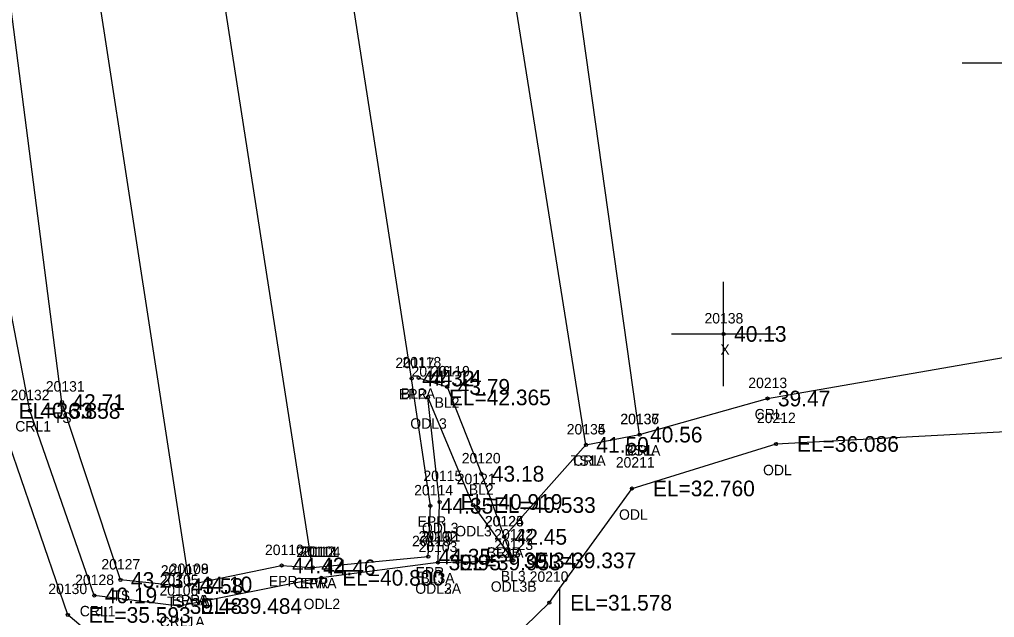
# Model space of a CAD drawing. Extents: x 2619569 to 2620117, y 784503 to 785150.
# Drawn here: x 2619804.3 to 2619897.7, y 784842.3 to 784899.6 of the extents above; entities that cross this region are included whole.
import ezdxf

# ---------------------------------------------------------------- set-up
doc = ezdxf.new("R2010")
doc.units = 0
for name, color, linetype in [('RD_DTM_BkLn1', 7, 'Continuous'), ('RD_DTM_BkLn2', 7, 'Continuous'), ('RD_DTM_BkLn_txCode', 7, 'Continuous'), ('RD_EX_H2O', 7, 'Continuous'), ('RD_EX_H2O_txCode', 7, 'Continuous'), ('RD_EX_Misc', 7, 'Continuous'), ('RD_EX_Misc_txCode', 7, 'Continuous'), ('RD_EX_Road', 7, 'Continuous'), ('RD_EX_Road_txCode', 7, 'Continuous'), ('RD_EX_TX_H2O_ELEV', 7, 'Continuous'), ('RD_EX_TX_Misc_ELEV', 7, 'Continuous'), ('RD_EX_TX_Road_ELEV', 7, 'Continuous'), ('RD_HC_Survey_ELEV', 7, 'Continuous'), ('RD_HC_Survey_txCode', 7, 'Continuous'), ('RD_SMD_Locator', 7, 'Continuous')]:
    doc.layers.add(name, color=color, linetype=linetype)

msp = doc.modelspace()

# ---------------------------------------------------------------- linework, layer by layer
at = {"layer": 'RD_DTM_BkLn1'}
for points in [[(2619832.403, 784847.117), (2619818.356, 784937.353), (2619803.195, 785033.818), (2619788.168, 785128.621)], [(2619842.547, 784865.279), (2619845.285, 784864.417), (2619848.555, 784856.083), (2619850.743, 784850.045)], [(2619844.412, 784847.589), (2619851.623, 784847.784), (2619850.743, 784850.045)]]:
    msp.add_lwpolyline(points, dxfattribs=at)
at = {"layer": 'RD_DTM_BkLn2'}
for points in [[(2619863.707, 784859.835), (2619852.265, 784941.112), (2619844.138, 785034.207), (2619822.185, 785133.612)], [(2619858.565, 784858.854), (2619845.668, 784939.8), (2619836.135, 785033.438), (2619815.075, 785132.906)], [(2619819.736, 784845.328), (2619814.007, 784845.916), (2619808.402, 784862.96), (2619799.163, 784934.374), (2619781.539, 785030.114), (2619769.886, 785089.145), (2619763.914, 785131.014)]]:
    msp.add_lwpolyline(points, dxfattribs=at)
at = {"layer": 'RD_EX_H2O'}
for points in [[(2619818.975, 784834.059), (2619808.965, 784842.559), (2619802.242, 784862.109), (2619788.776, 784932.49), (2619768.719, 785027.955), (2619758.968, 785087.806)], [(2619819.632, 784843.412), (2619811.497, 784844.429), (2619805.322, 784862.135), (2619791.728, 784933.025)], [(2619850.743, 784850.045), (2619858.565, 784858.854), (2619863.707, 784859.835), (2619875.949, 784863.297), (2619903.666, 784868.121), (2619924.462, 784867.36), (2619949.256, 784874.613), (2619971.299, 784850.547), (2619990.936, 784832.204), (2619978.094, 784805.139), (2619980.544, 784803.04), (2620013.789, 784776.159)], [(2619849.213, 784838.053), (2619855.055, 784843.735), (2619862.979, 784854.681), (2619876.772, 784858.944), (2619905.894, 784860.527), (2619923.246, 784863.85), (2619948.053, 784872.759), (2619969.079, 784848.673), (2619985.638, 784830.75), (2619975.853, 784807.963), (2619978.047, 784802.932), (2620013.477, 784773.679)], [(2619844.412, 784847.589), (2619844.558, 784853.388), (2619843.445, 784863.402), (2619847.748, 784853.09), (2619851.623, 784847.784)], [(2619844.412, 784847.589), (2619833.229, 784846.116), (2619819.632, 784843.412)]]:
    msp.add_lwpolyline(points, dxfattribs=at)
at = {"layer": 'RD_EX_Misc'}
for p, q in [((2619894.595, 784895.444), (2619904.595, 784895.444)), ((2619871.754, 784864.487), (2619871.754, 784874.487)), ((2619866.754, 784869.487), (2619876.754, 784869.487)), ((2619856.078, 784835.186), (2619856.078, 784845.186))]:
    msp.add_line(p, q, dxfattribs=at)
at = {"layer": 'RD_EX_Road'}
for points in [[(2619820.599, 784845.483), (2619829.428, 784847.299), (2619832.403, 784847.117), (2619843.469, 784848.147), (2619843.673, 784853.016), (2619841.879, 784865.21), (2619830.537, 784938.018), (2619815.779, 785030.404), (2619811.398, 785059.133), (2619800.292, 785130.224)], [(2619820.599, 784845.483), (2619806.714, 784935.634), (2619791.636, 785032.008), (2619776.959, 785126.604)]]:
    msp.add_lwpolyline(points, dxfattribs=at)
at = {"layer": 'RD_SMD_Locator'}
for centre in [(2619871.754, 784869.487), (2619842.547, 784865.279), (2619841.879, 784865.21), (2619845.285, 784864.417), (2619843.445, 784863.402), (2619808.402, 784862.96), (2619875.949, 784863.297), (2619805.322, 784862.135), (2619863.707, 784859.835), (2619863.707, 784859.835), (2619858.565, 784858.854), (2619858.565, 784858.854), (2619876.772, 784858.944), (2619848.555, 784856.083), (2619862.979, 784854.681), (2619844.558, 784853.388), (2619843.673, 784853.016), (2619847.748, 784853.09), (2619850.743, 784850.045), (2619850.743, 784850.045), (2619850.743, 784850.045), (2619843.469, 784848.147), (2619844.412, 784847.589), (2619844.412, 784847.589), (2619844.412, 784847.589), (2619851.623, 784847.784), (2619851.623, 784847.784), (2619829.428, 784847.299), (2619832.403, 784847.117), (2619832.403, 784847.117), (2619814.007, 784845.916), (2619833.229, 784846.116), (2619819.736, 784845.328), (2619820.599, 784845.483), (2619820.599, 784845.483), (2619811.497, 784844.429), (2619819.632, 784843.412), (2619819.632, 784843.412), (2619855.055, 784843.735), (2619808.965, 784842.559)]:
    msp.add_circle(centre, 0.15, dxfattribs=at)

# ---------------------------------------------------------------- texts
at = {"layer": 'RD_DTM_BkLn_txCode'}
for s, p in [('20118', (2619840.995, 784866.279)), ('20119', (2619843.734, 784865.417)), ('20131', (2619806.851, 784863.96)), ('BL2A', (2619840.854, 784863.279)), ('BL2', (2619844.081, 784862.417)), ('TS', (2619807.607, 784860.96)), ('20137', (2619861.872, 784860.835)), ('20135', (2619856.73, 784859.854)), ('20120', (2619846.681, 784857.083)), ('BS1A', (2619862.274, 784857.835)), ('TS1A', (2619857.116, 784856.854)), ('BL2', (2619847.35, 784854.083)), ('20126', (2619848.885, 784851.045)), ('20124', (2619848.909, 784851.045)), ('20103', (2619842.538, 784848.589)), ('20123', (2619849.788, 784848.784)), ('BL3B', (2619849.066, 784848.045)), ('BL2B', (2619849.066, 784848.045)), ('20127', (2619812.172, 784846.916)), ('20107', (2619817.862, 784846.328)), ('BL3', (2619850.418, 784845.784)), ('BL3A', (2619842.719, 784845.589)), ('TS', (2619813.212, 784843.916)), ('TSA', (2619818.452, 784843.328))]:
    msp.add_text(s, height=1, dxfattribs=at).set_placement(p)
at = {"layer": 'RD_EX_H2O_txCode'}
for s, p in [('20116', (2619841.87, 784865.402)), ('20213', (2619874.114, 784864.297)), ('20132', (2619803.487, 784863.135)), ('20136', (2619861.849, 784860.835)), ('CRL', (2619874.72, 784861.297)), ('20212', (2619874.938, 784860.944)), ('CRL1', (2619803.928, 784860.135)), ('ODL3', (2619841.752, 784860.402)), ('20134', (2619856.73, 784859.854)), ('CRL', (2619862.479, 784857.835)), ('CRL', (2619857.336, 784856.854)), ('20211', (2619861.428, 784856.681)), ('20115', (2619843.007, 784855.388)), ('20121', (2619846.197, 784855.09)), ('ODL', (2619875.528, 784855.944)), ('ODL', (2619861.735, 784851.681)), ('20125', (2619848.909, 784851.045)), ('20102', (2619842.538, 784849.589)), ('20101', (2619842.822, 784849.589)), ('ODL3', (2619842.865, 784850.388)), ('ODL3', (2619846.055, 784850.09)), ('20122', (2619849.788, 784849.784)), ('20104', (2619831.355, 784848.116)), ('CRLA', (2619849.027, 784848.045)), ('20210', (2619853.181, 784845.735)), ('20128', (2619809.662, 784845.429)), ('20105', (2619817.758, 784845.412)), ('20130', (2619807.091, 784844.559)), ('20106', (2619817.735, 784844.412)), ('ODL2A', (2619842.231, 784844.589)), ('ODL3A', (2619842.231, 784844.589)), ('ODL3B', (2619849.458, 784844.784)), ('ODL2', (2619831.536, 784843.116)), ('CRL1', (2619810.103, 784842.429)), ('CRL1A', (2619817.751, 784841.412))]:
    msp.add_text(s, height=1, dxfattribs=at).set_placement(p)
at = {"layer": 'RD_EX_Misc_txCode'}
for s, p in [('20138', (2619869.919, 784870.487)), ('X', (2619871.439, 784867.487))]:
    msp.add_text(s, height=1, dxfattribs=at).set_placement(p)
at = {"layer": 'RD_EX_Road_txCode'}
for s, p in [('20117', (2619840.328, 784866.21)), ('EPR', (2619840.65, 784863.21)), ('20114', (2619842.122, 784854.016)), ('EPR', (2619842.445, 784851.016)), ('20113', (2619841.918, 784849.147)), ('20110', (2619827.837, 784848.299)), ('20111', (2619831.135, 784848.117)), ('20108', (2619818.725, 784846.483)), ('20109', (2619818.725, 784846.483)), ('EPR', (2619842.24, 784846.147)), ('EPR', (2619828.199, 784845.299)), ('EPR', (2619831.174, 784845.117)), ('EPRA', (2619818.882, 784843.483)), ('EPLA', (2619818.906, 784843.483))]:
    msp.add_text(s, height=1, dxfattribs=at).set_placement(p)
at = {"layer": 'RD_EX_TX_H2O_ELEV'}
for s, p in [('EL=42.365', (2619845.445, 784862.652)), ('39.47', (2619876.949, 784862.547)), ('EL=36.858', (2619804.242, 784861.359)), ('40.33', (2619806.322, 784861.385)), ('40.56', (2619864.707, 784859.085)), ('41.50', (2619859.565, 784858.104)), ('EL=36.086', (2619878.772, 784858.194)), ('EL=32.760', (2619864.979, 784853.931)), ('EL=40.919', (2619846.558, 784852.638)), ('EL=40.533', (2619849.748, 784852.34)), ('42.45', (2619851.743, 784849.295)), ('EL=39.953', (2619846.412, 784846.839)), ('EL=39.953', (2619846.412, 784846.839)), ('EL=39.337', (2619853.623, 784847.034)), ('EL=40.800', (2619835.229, 784845.366)), ('40.19', (2619812.497, 784843.679)), ('39.48', (2619820.632, 784842.662)), ('EL=39.484', (2619821.632, 784842.662)), ('EL=31.578', (2619857.055, 784842.985)), ('EL=35.593', (2619810.965, 784841.809))]:
    msp.add_text(s, height=1.5, dxfattribs=at).set_placement(p)
at = {"layer": 'RD_EX_TX_Misc_ELEV'}
for s, p in [('40.13', (2619872.754, 784868.737)), ('44.14', (2619843.547, 784864.529)), ('43.79', (2619846.285, 784863.667)), ('42.71', (2619809.402, 784862.21)), ('40.56', (2619864.707, 784859.085)), ('41.50', (2619859.565, 784858.104)), ('43.18', (2619849.555, 784855.333)), ('42.45', (2619851.743, 784849.295)), ('42.45', (2619851.743, 784849.295)), ('39.95', (2619845.412, 784846.839)), ('39.34', (2619852.623, 784847.034)), ('43.23', (2619815.007, 784845.166)), ('43.58', (2619820.736, 784844.578))]:
    msp.add_text(s, height=1.5, dxfattribs=at).set_placement(p)
at = {"layer": 'RD_EX_TX_Road_ELEV'}
for s, p in [('44.32', (2619842.879, 784864.46)), ('44.35', (2619844.673, 784852.266)), ('44.35', (2619844.469, 784847.397)), ('44.42', (2619830.428, 784846.549)), ('44.46', (2619833.403, 784846.367)), ('44.10', (2619821.599, 784844.733)), ('44.10', (2619821.599, 784844.733))]:
    msp.add_text(s, height=1.5, dxfattribs=at).set_placement(p)
at = {"layer": 'RD_HC_Survey_ELEV'}
msp.add_text('44.46', height=1.5, dxfattribs=at).set_placement((2619833.403, 784846.367))
at = {"layer": 'RD_HC_Survey_txCode'}
for s, p in [('20112', (2619830.851, 784848.117)), ('CRWA', (2619830.599, 784845.117))]:
    msp.add_text(s, height=1, dxfattribs=at).set_placement(p)

doc.saveas('drawing.dxf')
